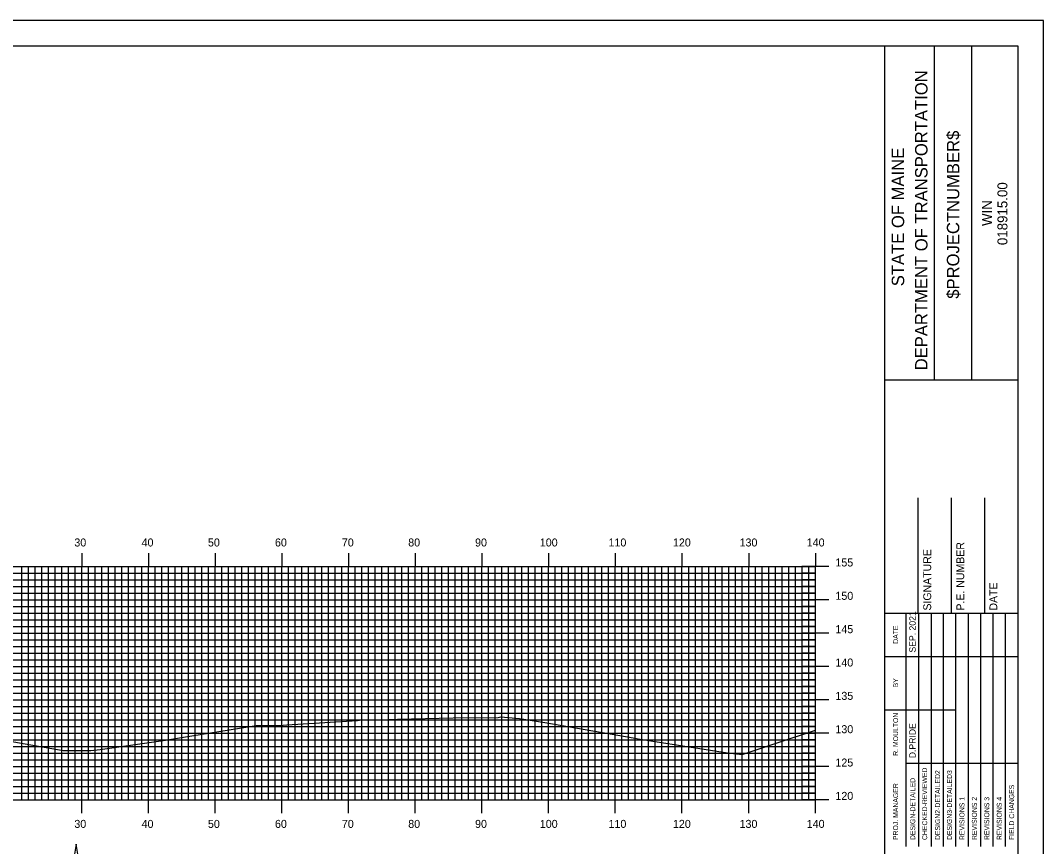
# Model space of a CAD drawing. Extents: x 850746 to 851089, y 366605 to 366825.
# Drawn here: x 850932.2 to 851085.6, y 366701.1 to 366824.9 of the extents above; entities that cross this region are included whole.
import ezdxf

# ---------------------------------------------------------------- set-up
doc = ezdxf.new("R2010")
doc.units = 0
for name, color, linetype in [('BORDER', 7, 'Continuous'), ('D_Drainage_Ditch_Line', 7, 'Continuous'), ('H_V ANNOTATION', 7, 'Continuous'), ('M_Roadway_Centerline', 7, 'Continuous'), ('MAJOR', 7, 'Continuous'), ('MINOR', 7, 'Continuous'), ('PLOT BOUNDARY', 7, 'Continuous'), ('S_Roadway_Centerline', 7, 'Continuous')]:
    doc.layers.add(name, color=color, linetype=linetype)

msp = doc.modelspace()

# ---------------------------------------------------------------- linework, layer by layer
at = {"layer": 'BORDER'}
for p, q in [((851061.83, 366611.06), (851061.83, 366821.06)), ((851069.28, 366771.05), (851069.28, 366821.05)), ((851074.87, 366771.05), (851074.87, 366821.05)), ((851061.83, 366771.04), (851081.83, 366771.04)), ((851066.83, 366736.06), (851066.83, 366753.36)), ((851071.83, 366736.06), (851071.83, 366753.36)), ((851076.83, 366736.06), (851076.83, 366753.36)), ((851061.83, 366736.06), (851081.83, 366736.06))]:
    msp.add_line(p, q, dxfattribs=at)
msp.add_lwpolyline([(850761.83, 366611.06), (851081.83, 366611.06), (851081.83, 366821.06), (850761.83, 366821.06)], close=True, dxfattribs=at)
for points in [[(851065.06, 366729.56), (851065.06, 366736.06)], [(851066.92, 366701.07), (851066.92, 366736.06)], [(851068.78, 366736.06), (851068.78, 366701.07)], [(851070.65, 366701.07), (851070.65, 366736.06)], [(851072.51, 366701.07), (851072.51, 366736.06)], [(851074.37, 366701.07), (851074.37, 366736.06)], [(851076.24, 366701.07), (851076.24, 366736.06)], [(851078.1, 366701.07), (851078.1, 366736.06)], [(851079.96, 366701.07), (851079.96, 366736.06)], [(851065.06, 366701.07), (851065.06, 366734.65)], [(851061.83, 366729.56), (851081.83, 366729.56)], [(851061.83, 366721.56), (851065.06, 366721.56)], [(851065.06, 366721.56), (851072.51, 366721.56)], [(851065.06, 366713.56), (851081.83, 366713.56)]]:
    msp.add_lwpolyline(points, dxfattribs=at)
at = {"layer": 'D_Drainage_Ditch_Line'}
msp.add_lwpolyline([(850939.92, 366697.5), (850941.23, 366697.5), (850940.57, 366701.44)], close=True, dxfattribs=at)
at = {"layer": 'MAJOR'}
for p, q in [((850941.43, 366745.06), (850941.43, 366743.06)), ((850951.43, 366745.06), (850951.43, 366743.06)), ((850961.43, 366745.06), (850961.43, 366743.06)), ((850971.43, 366745.06), (850971.43, 366743.06)), ((850981.43, 366745.06), (850981.43, 366743.06)), ((850991.43, 366745.06), (850991.43, 366743.06)), ((851001.43, 366745.06), (851001.43, 366743.06)), ((851011.43, 366745.06), (851011.43, 366743.06)), ((851021.43, 366745.06), (851021.43, 366743.06)), ((851031.43, 366745.06), (851031.43, 366743.06)), ((851041.43, 366745.06), (851041.43, 366743.06)), ((851051.43, 366745.06), (851051.43, 366743.06)), ((850771.43, 366743.06), (851051.43, 366743.06)), ((850771.43, 366743.06), (851051.43, 366743.06)), ((850941.43, 366708.06), (850941.43, 366743.06)), ((850951.43, 366708.06), (850951.43, 366743.06)), ((850961.43, 366708.06), (850961.43, 366743.06)), ((850971.43, 366708.06), (850971.43, 366743.06)), ((850981.43, 366708.06), (850981.43, 366743.06)), ((850991.43, 366708.06), (850991.43, 366743.06)), ((851001.43, 366708.06), (851001.43, 366743.06)), ((851011.43, 366708.06), (851011.43, 366743.06)), ((851021.43, 366708.06), (851021.43, 366743.06)), ((851031.43, 366708.06), (851031.43, 366743.06)), ((851041.43, 366708.06), (851041.43, 366743.06)), ((851053.43, 366743.06), (851049.42, 366743.06)), ((851051.43, 366708.06), (851051.43, 366743.06)), ((851051.43, 366708.06), (851051.43, 366743.06)), ((850771.43, 366738.06), (851051.43, 366738.06)), ((851053.43, 366738.06), (851049.42, 366738.06)), ((850771.43, 366733.06), (851051.43, 366733.06)), ((851053.43, 366733.06), (851049.42, 366733.06)), ((850771.43, 366728.06), (851051.43, 366728.06)), ((851053.43, 366728.06), (851049.42, 366728.06)), ((850771.43, 366723.06), (851051.43, 366723.06)), ((851053.43, 366723.06), (851049.42, 366723.06)), ((850771.43, 366718.06), (851051.43, 366718.06)), ((851053.43, 366718.06), (851049.42, 366718.06)), ((850771.43, 366713.06), (851051.43, 366713.06)), ((851053.43, 366713.06), (851049.42, 366713.06)), ((850771.43, 366708.06), (851051.43, 366708.06)), ((850771.43, 366708.06), (851051.43, 366708.06)), ((850941.43, 366706.05), (850941.43, 366708.06)), ((850951.43, 366706.05), (850951.43, 366708.06)), ((850961.43, 366706.05), (850961.43, 366708.06)), ((850971.43, 366706.05), (850971.43, 366708.06)), ((850981.43, 366706.05), (850981.43, 366708.06)), ((850991.43, 366706.05), (850991.43, 366708.06)), ((851001.43, 366706.05), (851001.43, 366708.06)), ((851011.43, 366706.05), (851011.43, 366708.06)), ((851021.43, 366706.05), (851021.43, 366708.06)), ((851031.43, 366706.05), (851031.43, 366708.06)), ((851041.43, 366706.05), (851041.43, 366708.06)), ((851053.43, 366708.06), (851049.42, 366708.06)), ((851051.43, 366706.05), (851051.43, 366708.06))]:
    msp.add_line(p, q, dxfattribs=at)
at = {"layer": 'MINOR'}
for p, q in [((850932.43, 366708.06), (850932.43, 366743.06)), ((850933.43, 366708.06), (850933.43, 366743.06)), ((850934.43, 366708.06), (850934.43, 366743.06)), ((850935.43, 366708.06), (850935.43, 366743.06)), ((850936.43, 366708.06), (850936.43, 366743.06)), ((850937.43, 366708.06), (850937.43, 366743.06)), ((850938.43, 366708.06), (850938.43, 366743.06)), ((850939.43, 366708.06), (850939.43, 366743.06)), ((850940.43, 366708.06), (850940.43, 366743.06)), ((850942.43, 366708.06), (850942.43, 366743.06)), ((850943.43, 366708.06), (850943.43, 366743.06)), ((850944.43, 366708.06), (850944.43, 366743.06)), ((850945.43, 366708.06), (850945.43, 366743.06)), ((850946.43, 366708.06), (850946.43, 366743.06)), ((850947.43, 366708.06), (850947.43, 366743.06)), ((850948.43, 366708.06), (850948.43, 366743.06)), ((850949.43, 366708.06), (850949.43, 366743.06)), ((850950.43, 366708.06), (850950.43, 366743.06)), ((850952.43, 366708.06), (850952.43, 366743.06)), ((850953.43, 366708.06), (850953.43, 366743.06)), ((850954.43, 366708.06), (850954.43, 366743.06)), ((850955.43, 366708.06), (850955.43, 366743.06)), ((850956.43, 366708.06), (850956.43, 366743.06)), ((850957.43, 366708.06), (850957.43, 366743.06)), ((850958.43, 366708.06), (850958.43, 366743.06)), ((850959.43, 366708.06), (850959.43, 366743.06)), ((850960.43, 366708.06), (850960.43, 366743.06)), ((850962.43, 366708.06), (850962.43, 366743.06)), ((850963.43, 366708.06), (850963.43, 366743.06)), ((850964.43, 366708.06), (850964.43, 366743.06)), ((850965.43, 366708.06), (850965.43, 366743.06)), ((850966.43, 366708.06), (850966.43, 366743.06)), ((850967.43, 366708.06), (850967.43, 366743.06)), ((850968.43, 366708.06), (850968.43, 366743.06)), ((850969.43, 366708.06), (850969.43, 366743.06)), ((850970.43, 366708.06), (850970.43, 366743.06)), ((850972.43, 366708.06), (850972.43, 366743.06)), ((850973.43, 366708.06), (850973.43, 366743.06)), ((850974.43, 366708.06), (850974.43, 366743.06)), ((850975.43, 366708.06), (850975.43, 366743.06)), ((850976.43, 366708.06), (850976.43, 366743.06)), ((850977.43, 366708.06), (850977.43, 366743.06)), ((850978.43, 366708.06), (850978.43, 366743.06)), ((850979.43, 366708.06), (850979.43, 366743.06)), ((850980.43, 366708.06), (850980.43, 366743.06)), ((850982.43, 366708.06), (850982.43, 366743.06)), ((850983.43, 366708.06), (850983.43, 366743.06)), ((850984.43, 366708.06), (850984.43, 366743.06)), ((850985.43, 366708.06), (850985.43, 366743.06)), ((850986.43, 366708.06), (850986.43, 366743.06)), ((850987.43, 366708.06), (850987.43, 366743.06)), ((850988.43, 366708.06), (850988.43, 366743.06)), ((850989.43, 366708.06), (850989.43, 366743.06)), ((850990.43, 366708.06), (850990.43, 366743.06)), ((850992.43, 366708.06), (850992.43, 366743.06)), ((850993.43, 366708.06), (850993.43, 366743.06)), ((850994.43, 366708.06), (850994.43, 366743.06)), ((850995.43, 366708.06), (850995.43, 366743.06)), ((850996.43, 366708.06), (850996.43, 366743.06)), ((850997.43, 366708.06), (850997.43, 366743.06)), ((850998.43, 366708.06), (850998.43, 366743.06)), ((850999.43, 366708.06), (850999.43, 366743.06)), ((851000.43, 366708.06), (851000.43, 366743.06)), ((851002.43, 366708.06), (851002.43, 366743.06)), ((851003.43, 366708.06), (851003.43, 366743.06)), ((851004.43, 366708.06), (851004.43, 366743.06)), ((851005.43, 366708.06), (851005.43, 366743.06)), ((851006.43, 366708.06), (851006.43, 366743.06)), ((851007.43, 366708.06), (851007.43, 366743.06)), ((851008.43, 366708.06), (851008.43, 366743.06)), ((851009.43, 366708.06), (851009.43, 366743.06)), ((851010.43, 366708.06), (851010.43, 366743.06)), ((851012.43, 366708.06), (851012.43, 366743.06)), ((851013.43, 366708.06), (851013.43, 366743.06)), ((851014.43, 366708.06), (851014.43, 366743.06)), ((851015.43, 366708.06), (851015.43, 366743.06)), ((851016.43, 366708.06), (851016.43, 366743.06)), ((851017.43, 366708.06), (851017.43, 366743.06)), ((851018.43, 366708.06), (851018.43, 366743.06)), ((851019.43, 366708.06), (851019.43, 366743.06)), ((851020.43, 366708.06), (851020.43, 366743.06)), ((851022.43, 366708.06), (851022.43, 366743.06)), ((851023.43, 366708.06), (851023.43, 366743.06)), ((851024.43, 366708.06), (851024.43, 366743.06)), ((851025.43, 366708.06), (851025.43, 366743.06)), ((851026.43, 366708.06), (851026.43, 366743.06)), ((851027.43, 366708.06), (851027.43, 366743.06)), ((851028.43, 366708.06), (851028.43, 366743.06)), ((851029.43, 366708.06), (851029.43, 366743.06)), ((851030.43, 366708.06), (851030.43, 366743.06)), ((851032.43, 366708.06), (851032.43, 366743.06)), ((851033.43, 366708.06), (851033.43, 366743.06)), ((851034.43, 366708.06), (851034.43, 366743.06)), ((851035.43, 366708.06), (851035.43, 366743.06)), ((851036.43, 366708.06), (851036.43, 366743.06)), ((851037.43, 366708.06), (851037.43, 366743.06)), ((851038.43, 366708.06), (851038.43, 366743.06)), ((851039.43, 366708.06), (851039.43, 366743.06)), ((851040.43, 366708.06), (851040.43, 366743.06)), ((851042.43, 366708.06), (851042.43, 366743.06)), ((851043.43, 366708.06), (851043.43, 366743.06)), ((851044.43, 366708.06), (851044.43, 366743.06)), ((851045.43, 366708.06), (851045.43, 366743.06)), ((851046.43, 366708.06), (851046.43, 366743.06)), ((851047.43, 366708.06), (851047.43, 366743.06)), ((851048.43, 366708.06), (851048.43, 366743.06)), ((851049.43, 366708.06), (851049.43, 366743.06)), ((851050.43, 366708.06), (851050.43, 366743.06)), ((850771.43, 366742.06), (851051.43, 366742.06)), ((851051.43, 366742.06), (851049.42, 366742.06)), ((850771.43, 366741.06), (851051.43, 366741.06)), ((850771.43, 366740.06), (851051.43, 366740.06)), ((851051.43, 366741.06), (851049.42, 366741.06)), ((851051.43, 366740.06), (851049.42, 366740.06)), ((850771.43, 366739.06), (851051.43, 366739.06)), ((851051.43, 366739.06), (851049.42, 366739.06)), ((850771.43, 366737.06), (851051.43, 366737.06)), ((851051.43, 366737.06), (851049.42, 366737.06)), ((850771.43, 366736.06), (851051.43, 366736.06)), ((851051.43, 366736.06), (851049.42, 366736.06)), ((850771.43, 366735.06), (851051.43, 366735.06)), ((850771.43, 366734.06), (851051.43, 366734.06)), ((851051.43, 366735.06), (851049.42, 366735.06)), ((851051.43, 366734.06), (851049.42, 366734.06)), ((850771.43, 366732.06), (851051.43, 366732.06)), ((850771.43, 366731.06), (851051.43, 366731.06)), ((851051.43, 366732.06), (851049.42, 366732.06)), ((851051.43, 366731.06), (851049.42, 366731.06)), ((850771.43, 366730.06), (851051.43, 366730.06)), ((851051.43, 366730.06), (851049.42, 366730.06)), ((850771.43, 366729.06), (851051.43, 366729.06)), ((851051.43, 366729.06), (851049.42, 366729.06)), ((850771.43, 366727.06), (851051.43, 366727.06)), ((850771.43, 366726.06), (851051.43, 366726.06)), ((851051.43, 366727.06), (851049.42, 366727.06)), ((851051.43, 366726.06), (851049.42, 366726.06)), ((850771.43, 366725.06), (851051.43, 366725.06)), ((851051.43, 366725.06), (851049.42, 366725.06)), ((850771.43, 366724.06), (851051.43, 366724.06)), ((851051.43, 366724.06), (851049.42, 366724.06)), ((850771.43, 366722.06), (851051.43, 366722.06)), ((851051.43, 366722.06), (851049.42, 366722.06)), ((850771.43, 366721.06), (851051.43, 366721.06)), ((850771.43, 366720.06), (851051.43, 366720.06)), ((851051.43, 366721.06), (851049.42, 366721.06)), ((851051.43, 366720.06), (851049.42, 366720.06)), ((850771.43, 366719.06), (851051.43, 366719.06)), ((851051.43, 366719.06), (851049.42, 366719.06)), ((850771.43, 366717.06), (851051.43, 366717.06)), ((851051.43, 366717.06), (851049.42, 366717.06)), ((850771.43, 366716.06), (851051.43, 366716.06)), ((851051.43, 366716.06), (851049.42, 366716.06)), ((850771.43, 366715.06), (851051.43, 366715.06)), ((850771.43, 366714.06), (851051.43, 366714.06)), ((851051.43, 366715.06), (851049.42, 366715.06)), ((851051.43, 366714.06), (851049.42, 366714.06)), ((850771.43, 366712.06), (851051.43, 366712.06)), ((850771.43, 366711.06), (851051.43, 366711.06)), ((851051.43, 366712.06), (851049.42, 366712.06)), ((851051.43, 366711.06), (851049.42, 366711.06)), ((850771.43, 366710.06), (851051.43, 366710.06)), ((851051.43, 366710.06), (851049.42, 366710.06)), ((850771.43, 366709.06), (851051.43, 366709.06)), ((851051.43, 366709.06), (851049.42, 366709.06))]:
    msp.add_line(p, q, dxfattribs=at)
at = {"layer": 'PLOT BOUNDARY'}
msp.add_lwpolyline([(850745.64, 366604.94), (851085.64, 366604.94), (851085.64, 366824.94), (850745.64, 366824.94)], close=True, dxfattribs=at)
at = {"layer": 'S_Roadway_Centerline'}
msp.add_lwpolyline([(850928.35, 366717.27), (850938.64, 366715.45), (850941.29, 366715.46), (850942.8, 366715.46), (850944.2, 366715.63), (850953.99, 366717.03), (850956.67, 366717.47), (850967.59, 366719.2), (850970.65, 366719.22), (850971.64, 366719.26), (850972.17, 366719.3), (850982.79, 366719.94), (850983.07, 366720.03), (850986.01, 366720.07), (850988.79, 366720.17), (850997.11, 366720.34), (851003.86, 366720.43), (851004.25, 366720.51), (851007.08, 366720.24), (851010.86, 366719.66), (851024.43, 366717.3), (851024.88, 366717.22), (851026.45, 366716.96), (851026.75, 366716.94), (851038.26, 366715.14), (851040.04, 366714.92), (851040.59, 366714.94), (851045.69, 366716.64), (851051.43, 366718.51)], dxfattribs=at)

# ---------------------------------------------------------------- texts
at = {"layer": 'BORDER'}
for s, height, p in [('DEPARTMENT OF TRANSPORTATION', 1.8635, (851068.24, 366772.47)), ('$PROJECTNUMBER$', 1.8635, (851073.01, 366783.21)), ('STATE OF MAINE', 1.8635, (851064.74, 366785.08)), ('018915.00', 1.491, (851080.22, 366791.25)), ('WIN', 1.491, (851077.9, 366794.12)), ('P.E. NUMBER', 1.1811, (851073.75, 366736.45)), ('SIGNATURE', 1.181, (851068.79, 366736.45)), ('DATE', 1.181, (851078.71, 366736.45)), ('SEP. 2021', 0.969, (851066.47, 366730.15)), ('DATE', 0.743, (851063.83, 366731.47)), ('BY', 0.743, (851063.83, 366724.93)), ('R. MOULTON', 0.745, (851063.83, 366714.67)), ('D.PRIDE', 0.969, (851066.47, 366714.31)), ('CHECKED-REVIEWED', 0.7455, (851068.19, 366702.04)), ('DESIGN-DETAILED', 0.7455, (851066.4, 366702.04)), ('DESIGN2-DETAILED2', 0.7455, (851070.13, 366702.04)), ('DESIGN3-DETAILED3', 0.7455, (851071.91, 366702.04)), ('PROJ. MANAGER', 0.7455, (851063.83, 366702.04)), ('FIELD CHANGES', 0.7455, (851081.23, 366702.04)), ('REVISIONS 1', 0.7455, (851073.78, 366702.04)), ('REVISIONS 2', 0.7455, (851075.64, 366702.04)), ('REVISIONS 3', 0.7455, (851077.5, 366702.04)), ('REVISIONS 4', 0.7455, (851079.37, 366702.04))]:
    msp.add_text(s, height=height, rotation=90, dxfattribs=at).set_placement(p)
at = {"layer": 'H_V ANNOTATION'}
for s, p in [('30', (850940.32, 366746.06)), ('40', (850950.4, 366746.06)), ('50', (850960.35, 366746.06)), ('60', (850970.4, 366746.06)), ('70', (850980.43, 366746.06)), ('80', (850990.38, 366746.06)), ('90', (851000.4, 366746.06)), ('100', (851010.11, 366746.06)), ('110', (851020.41, 366746.06)), ('120', (851030.07, 366746.06)), ('130', (851040.06, 366746.06)), ('140', (851050.13, 366746.06)), ('155', (851054.43, 366743.06)), ('150', (851054.43, 366738.06)), ('145', (851054.43, 366733.06)), ('140', (851054.43, 366728.06)), ('135', (851054.43, 366723.06)), ('130', (851054.43, 366718.06)), ('125', (851054.43, 366713.06)), ('120', (851054.43, 366708.06)), ('30', (850940.32, 366703.86)), ('40', (850950.4, 366703.86)), ('50', (850960.35, 366703.86)), ('60', (850970.4, 366703.86)), ('70', (850980.43, 366703.86)), ('80', (850990.38, 366703.86)), ('90', (851000.4, 366703.86)), ('100', (851010.11, 366703.86)), ('110', (851020.41, 366703.86)), ('120', (851030.07, 366703.86)), ('130', (851040.06, 366703.86)), ('140', (851050.13, 366703.86))]:
    msp.add_text(s, height=1.2, dxfattribs=at).set_placement(p)
at = {"layer": 'M_Roadway_Centerline'}
for s, p in [('C', (850983.06, 366720.03)), ('L', (850983.07, 366720.02))]:
    msp.add_text(s, height=0.0146, dxfattribs=at).set_placement(p)

doc.saveas('drawing.dxf')
